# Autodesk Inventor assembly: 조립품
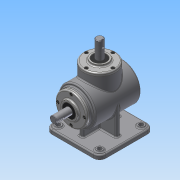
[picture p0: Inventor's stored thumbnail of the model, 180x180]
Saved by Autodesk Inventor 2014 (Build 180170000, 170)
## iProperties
Created: 2015-07
Part Number: 조립품
Document SubType Name: Assembly
Designer: nert
Author: nert
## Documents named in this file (14)
- C:\Users\nert\Desktop\조립품.iam
- C:\Users\nert\Desktop\본체.ipt
- C:\Users\nert\Desktop\450705V1013\서브 축.ipt
- 서브 축.ipt
- C:\Users\nert\Desktop\450705V1013\커버.ipt
- C:\Users\nert\Desktop\450705V1013\베어링 6203.ipt
- C:\Users\nert\Desktop\450705V1013\키 4x4.ipt
- C:\Users\nert\Desktop\450705V1013\서브 베벨기어.ipt
- C:\Users\nert\Desktop\450705V1013\오일실.ipt
- C:\Users\nert\Desktop\450705V1013\메인 베벨기어.ipt
- C:\Users\nert\Desktop\450705V1013\메인 축.ipt
- 메인 축.ipt
- C:\Users\nert\Desktop\450705V1013\키 5x5.ipt
- C:\Users\nert\Desktop\450705V1013\M4.ipt
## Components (8 placed, 1 different names)
1. M4:1
2. M4:3
3. M4:4
4. M4:5
5. M4:2
6. M4:6
7. M4:7
8. M4:8
